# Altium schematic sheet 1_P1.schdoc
size 309 x 223 mm; Symbol: Sheet-Symbol_A4; Device: Sheet-Symbol_A4; Company: EasyEDA.com; Drawed: EasyEDA Pro; Reviewed: EasyEDA Pro; Version: V0.1; Page Size: A4; @Project Name: IoT_Button_2023-05-27_11-22-50; @Page Count: 1; @Update Date: 2023-05-29; @Create Date: 2023-05-27; @Schematic Name: Schematic1; Part Number: JLCPCB-002; @Page No: 1; @Page Name: P1
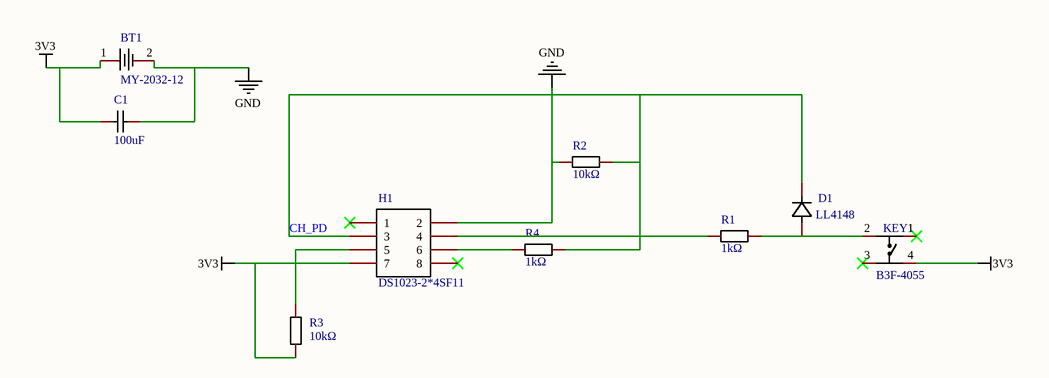
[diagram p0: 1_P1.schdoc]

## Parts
BT1  MY-2032-12  [BAT-SMD_MY-2032-12]
C1  100uF  [C0805]
D1  LL4148  [LL-34_L3.4-W1.5-RD]
H1  DS1023-2*4SF11  [HDR-TH_8P-P2.54-V-F-R2-C4-S2.54-1]
KEY1  B3F-4055  [KEY-TH_4P-L12.0-W12.0-P5.00-LS13.4-EH]
R1  1kΩ  [R0805]
R2  10kΩ  [R0805]
R3  10kΩ  [R0805]
R4  1kΩ  [R0805]

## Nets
3V3: BT1.1 C1.1 H1.7 KEY1.4 R3.1
GND: BT1.2 C1.2 H1.2 R2.1
CH_PD: D1.1(K) H1.3 R2.2 R4.2
NetD1_2: D1.2(A) KEY1.2 R1.2
NetH1_4: H1.4 R1.1
NetH1_5: H1.5 R3.2
NetH1_6: H1.6 R4.1

Not connected (* = marked no-connect by the designer): H1 1* 8*; KEY1 1* 3*

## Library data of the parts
BT1 = MY-2032-12: Manufacturer: MYOUNG(美阳); Add into BOM: yes
C1 = GRM21BR60J107ME15L: Capacitance: Tolerance:±20% Tolerance:±20% Voltage Rated: Temperature Coefficient:; Manufacturer: muRata(村田); Add into BOM: yes; Tolerance: ±20%
D1 = LL4148_C2857181: Diode Configuration: Power Dissipation: Reverse Voltage (Vr): Average Rectified Current (Io): Forward Voltage (Vf@If):- Reverse Leakage Current:5uA@75V Reverse Recovery Time (trr): Operating Temperature:+175℃@(Tj) Operating Temperature:+175℃@(Tj); Manufacturer: JSMSEMI(杰盛微); Add into BOM: yes
H1 = DS1023-2*4SF11: Number of Rows:双排 Number of Holes:8 Pitch:2.54mm Holes Structure:2x4P Row Spacing:2.54mm Mounting Type:Straight Insulation Height:- Contact Material:- Contact Plating:-; Manufacturer: CONNFLY; Add into BOM: yes; Number of Holes: 8; Pitch: 2.54mm; Holes Structure: 2x4P
KEY1 = B3F-4055_C84931: Contact Current:50mA Voltage Rating (DC):24V Circuit:SPST Mounting Style:Straight Actuator Style:Square Plunger With Lamp:- Mechanical Life:- Switch Length:12mm Switch Width:12mm Switch Height:7.3mm; Manufacturer: OMRON(欧姆龙); Add into BOM: yes; Contact Current: 50mA; Voltage Rating (DC): 24V; Circuit: SPST; Switch Length: 12mm; Switch Height: 7.3mm
R1 R4 = 0805W8F1001T5E: Type:Thick Film Resistors Resistance: Tolerance:±1% Tolerance:±1% Power(Watts): Temperature Coefficient:±100ppm/℃ Temperature Coefficient:±100ppm/℃ Overload Voltage (Max): Operating Temperature Range:-55℃~+155℃ Operating Temperature Range:-55℃~+155℃; Manufacturer: UNI-ROYAL(厚声); Add into BOM: yes; Tolerance: ±1%
R2 R3 = 0805W8F1002T5E: Type:Thick Film Resistors Resistance: Tolerance:±1% Tolerance:±1% Power(Watts): Temperature Coefficient:±100ppm/℃ Temperature Coefficient:±100ppm/℃ Overload Voltage (Max): Operating Temperature Range:-55℃~+155℃ Operating Temperature Range:-55℃~+155℃; Manufacturer: UNI-ROYAL(厚声); Add into BOM: yes; Tolerance: ±1%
